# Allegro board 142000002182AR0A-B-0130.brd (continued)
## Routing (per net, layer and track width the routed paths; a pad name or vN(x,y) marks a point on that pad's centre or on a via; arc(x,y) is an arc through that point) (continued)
FAN6_SENSOR_OUT: length 312.7
  TOP w0.127: 136.37,18.36 135.83,18.91 135.05,18.91 U7.B7
  TOP w0.254: v3(406.44,36.45) 406.4,36.45 405.38,37.47 398.48,37.47 396.34,39.61 392.09,39.61 390.41,41.29 390.41,42.48 R165.2 ; v3(139.5,19.28) 139.47,19.28 139.24,19.05 138.68,19.05 138,18.36 136.37,18.36
  BOTTOM w0.254: v3(139.5,19.28) 139.8,19.58 140.87,19.58 141.22,19.94 142.72,19.94 143.69,18.97 147.49,18.97 150.11,16.35 150.11,16.34 150.45,16 v1(153.29,16) 154.69,14.61 154.69,10.92 156.71,8.89 174.12,8.89 178.97,13.74 241.88,13.74 244.39,16.26 295.31,16.26 297.67,13.89 335.47,13.89 340.68,19.1 378.05,19.1 385.87,26.92 390.63,26.92 399.31,35.61 405.6,35.61 v3(406.44,36.45)
FAN6_SENSOR_OUT_R: length 8.7
  TOP w0.254: R165.1 v3(390.78,44.83)
  BOTTOM w0.254: U21.1 391.27,48.12 390.78,47.62 v3(390.78,44.83) 390.02,44.83 v1(389.76,45.09)
FAN6F_VCP: length 3.8
  TOP w0.254: C131.2 385.7,28.96 v3(384.68,29.97) 384.29,30.36 U22.4
  BOTTOM w0.254: v1(385.7,29.97) v3(384.68,29.97)
FAN6R_VCP: length 3.5
  TOP w0.254: v1(375.72,28.07) v3(374.93,28.86) 374.64,29.15 U19.4
  BOTTOM w0.254: v3(374.93,28.86) v1(375.72,28.07)
FAN7_LED_G: length 141.9
  TOP w0.254: U7.K11 v2(127.88,14.94) ; CONN1.5 v3(5.29,32.98)
  BOTTOM w0.254: v3(5.29,32.98) 7.03,31.24 v1(7.03,29.21) 7.03,28.46 9.08,26.42 13.76,26.42 21.51,18.67 27.18,18.67 28.19,17.65 48.22,17.65 51.78,21.21 79.37,21.21 91.51,9.07 114.86,9.07 118.11,12.32 123.74,12.32 125.77,14.35 127.29,14.35 v2(127.88,14.94)
FAN7_LED_R: length 143.4
  TOP w0.254: v3(128.79,11.67) 129.08,11.96 U7.J13 ; v3(5.21,31.62) 5.29,31.71 CONN1.7
  BOTTOM w0.254: v3(128.79,11.67) 125.24,11.67 125.1,11.81 118.32,11.81 115.07,8.56 91.3,8.56 79.15,20.7 51.99,20.7 48.43,17.14 27.98,17.14 26.97,18.16 21.3,18.16 13.68,25.78 8.64,25.78 v1(7.24,27.17) 4.83,29.59 4.83,31.24 v3(5.21,31.62)
FAN7_PRESENT: length 155.6
  TOP w0.127: 131.06,13.21 131.06,14.16 U7.G12
  TOP w0.254: v3(131.3,9.09) 131.18,9.09 130.64,9.63 130.64,11.13 131.06,11.55 131.06,13.21 ; v3(12.32,11.56) 12.45,11.43 12.45,10.54 12.83,10.16 15.57,10.16 15.82,10.41 R4.1 24.38,11.05 v3(26.04,9.4) ; CONN1.21 v3(5.25,22.82)
  BOTTOM w0.254: v3(131.3,9.09) 131.18,9.09 130.09,8 126.03,8 123.85,5.82 91.16,5.82 78.31,18.67 52.83,18.67 49.27,15.11 31.75,15.11 v1(30.26,13.62) v3(26.04,9.4) ; v3(5.25,22.82) 6.14,22.82 7.24,21.72 7.24,15.5 11.44,11.3 12.06,11.3 v3(12.32,11.56)
FAN7_PWM: length 135.4
  TOP w0.254: Q2.2 17.97,38.48 v3(20.06,36.39) ; U7.L4 v2(127.08,20.54)
  BOTTOM w0.254: v3(20.06,36.39) 18.77,35.1 18.77,33.12 16.38,30.73 16.38,26.67 22.35,20.7 43.47,20.7 v1(48.05,25.27) 49.42,23.9 79.55,23.9 84.27,19.18 111.97,19.18 114.13,21.34 121.39,21.34 123.7,19.02 124.17,19.02 125.59,20.45 126.99,20.45 v2(127.08,20.54)
FAN7_SENSOR_IN: length 138.3
  TOP w0.254: U7.M13 126.57,13.74 125.68,12.86 125.64,12.86 124.74,11.96 119.45,11.96 119.42,11.94 110.23,11.94 106.57,15.6 85.56,15.6 84.64,16.51 79.18,21.97 51.6,21.97 47.13,17.5 19.28,17.5 v3(16.89,15.11) R1.1 ; v3(5.21,27.94) 5.25,27.9 CONN1.13
  BOTTOM w0.254: v3(16.89,15.11) 16.89,15.37 v1(16.26,16) 11.68,20.57 11.68,21.64 7.03,26.29 6.86,26.29 v3(5.21,27.94)
FAN7_SENSOR_OUT: length 140.8
  TOP w0.127: U7.L12 127.08,14.14 127.08,13.52 126.86,13.31
  TOP w0.254: CONN1.15 5.25,26.63 v3(5.21,26.67) ; 126.86,13.31 125.62,12.06 125.48,12.06 124.87,11.46 119.66,11.46 119.63,11.43 110.02,11.43 106.36,15.09 85.35,15.09 84.43,16 78.97,21.46 51.87,21.46 47.39,16.99 20.29,16.99 v3(17.15,13.84) R2.1
  BOTTOM w0.254: v3(5.21,26.67) 6.22,25.65 6.95,25.65 11.18,21.43 11.18,20 v1(12.1,19.08) 12.1,18.97 17.15,13.92 v3(17.15,13.84)
FAN8_LED_G: length 130.1
  TOP w0.127: 125.22,17.02 125.51,17.31 126.25,17.31 U7.M8
  TOP w0.254: 125.22,17.02 123.95,17.02 123.16,16.23 112.56,16.23 108.62,20.17 87.45,20.17 81.08,26.54 53.09,26.54 v3(48.77,22.23) 47.5,22.23 45.59,20.32 19.43,20.32 14.48,25.27 14.48,28.7 12.74,30.44 CONN1.10
  BOTTOM w0.254: v3(48.77,22.23) v1(49.41,21.58)
FAN8_LED_R: length 128.9
  TOP w0.254: U7.N9 125.32,16.38 123.83,16.38 123.16,15.72 112.05,15.72 108.11,19.66 87.24,19.66 80.87,26.04 53.51,26.04 49.04,21.56 47.98,21.56 v3(46.86,20.45) 46.23,19.81 19.22,19.81 13.97,25.06 13.97,28.49 13.29,29.17 CONN1.12
  BOTTOM w0.254: v3(46.86,20.45) v1(45.95,20.45)
FAN8_PRESENT: length 142.2
  TOP w0.127: 130.05,12.56 130.05,13.33 130.27,13.55 130.27,15.73 U7.G10
  TOP w0.254: v3(127.75,9.41) 129,10.67 129.05,10.67 130.01,11.62 130.01,12.52 130.05,12.56 ; CONN1.24 12.36,21.55 13.33,20.58 13.33,13.36 13.59,13.11 15.57,13.11 15.82,12.85 R3.1 24.77,12.45 v3(25.53,13.21)
  BOTTOM w0.254: v3(25.53,13.21) v1(26.29,13.97) 28.45,16.13 48.85,16.13 52.41,19.68 78.73,19.68 91.59,6.83 123.42,6.83 125.89,9.29 127.63,9.29 v3(127.75,9.41)
FAN8_PWM: length 130.7
  TOP w0.254: v3(14.86,30.35) 15.24,30.74 15.24,34.32 Q1.2 ; U7.L5 v2(127.08,19.74)
  BOTTOM w0.254: v3(14.86,30.35) 15.2,30.01 15.2,26.42 21.93,19.68 27.81,19.68 v1(29.08,18.41) 29.34,18.67 42.88,18.67 47.1,22.89 79.13,22.89 83.85,18.16 112.39,18.16 114.55,20.32 120.97,20.32 123.28,18.01 124.21,18.01 125.94,19.74 v2(127.08,19.74)
FAN8_SENSOR_IN: length 127.6
  TOP w0.127: 125.35,15.88 125.45,15.77 126.31,15.77 U7.M10
  TOP w0.254: CONN1.18 12.11,25.36 14.77,22.69 14.77,20.32 15.02,20.07 R5.1 15.04,20.25 15.52,20.73 17.59,20.73 19.01,19.3 47.5,19.3 52.71,24.51 80.23,24.51 86.61,18.14 108.7,18.14 v3(111.23,15.6) 111.62,15.21 123.29,15.21 123.95,15.88 125.35,15.88
  BOTTOM w0.254: v1(110.74,16.51) 110.74,16.09 v3(111.23,15.6)
FAN8_SENSOR_OUT: length 126.6
  TOP w0.254: U7.N11 125.74,15.48 124.48,15.48 123.7,14.71 111.2,14.71 v3(109.22,16.68) 108.28,17.63 86.4,17.63 80.02,24 52.92,24 46.92,18.01 15.29,18.01 15.04,18.26 R6.1 13.97,19.74 13.97,22.23 12.11,24.09 CONN1.20
  BOTTOM w0.254: v1(108.29,16.69) 108.3,16.68 v3(109.22,16.68)
FAN_12V: length 55.2
  TOP w0.254: 378.33,5.46 378.2,5.6 U20.9
  TOP w0.381: 381.63,25.02 381.58,24.97 C127.2 ; v3(379.65,25.46) 379.65,25.45 379.71,25.4 379.71,25.04 379.78,24.97 C127.2 ; L26.1 380.62,25.53 C127.2 ; L20.1 304.35,22.91 C101.2 305.56,22.1 ; L24.1 368.61,28.27 C117.2 367.03,29.84 v3(366.9,29.72) ; v3(313.72,21.59) 314.07,21.95 C108.2 315.03,22.53 315.09,22.48 ; R12.2 42.55,41.4 43.16,40.79 43.16,37.68 44.07,36.77 L4.1
  TOP w0.508: C13.2 36.76,25.71 36.7,25.65 ; C13.2 38.68,25.71 v3(38.73,25.65) ; C13.2 37.85,25.33 v3(37.85,24.77) ; C32.2 104.45,30.66 104.52,30.73 ; C32.2 103.3,30.66 v3(102.74,30.1) ; C32.2 103.63,29.46 L7.1 ; C65.1 211.43,24.74 C67.1 212.12,24.36 212.22,24.26 ; C88.2 241.05,30.1 L18.1 ; C88.2 241.63,31.55 241.81,31.37 ; C88.2 240.34,31.55 ; 166.8,25.71 C46.2 ; C46.2 165.66,25.71 165.48,25.53 ; C46.2 166.12,25.02 ; 175.01,25.53 175.19,25.71 C54.2 ; C68.1 213.13,24.66 213.11,24.64 ; 86.36,38.86 86.41,38.81 C25.2 ; 392.81,6.99 392.94,6.86 C136.1 393.12,5.84 394.08,5.84 ; C135.1 391.8,6.86 ; 378.33,5.46 378.33,5.46 380.91,5.46 D3.C ; 389.64,5.71 389.69,5.66 C134.1 390.65,6.73 390.78,6.86 ; C25.2 86.41,37.01 v3(86.36,36.96) ; C25.2 86.03,37.85 v3(85.47,37.85) ; v3(27.81,24.89) 27.81,25.33 C5.2 26.92,25.2 v3(26.92,24.89) ; 223.45,38.43 C78.2 ; R119.2 v3(225.7,24.61) ; C54.2 175.64,25.02 ; C54.2 176.33,25.71
  vias: v1(35.56,24.64) v1(96.77,31.5) v1(166.5,24.89) v1(240.28,30.23) v1(371.98,7.62) v3(26.92,24) v3(27.81,24) v3(28.83,24.89) v3(33.66,34.77) v3(34.47,34.77) v3(35.2,36.88) v3(35.2,36.07) v3(35.2,35.26) v3(36.96,24.77) v3(38.73,24.77) v3(38.73,23.88) v3(43.69,34.77) v3(44.5,34.77) v3(45.24,36.88) v3(45.24,36.07) v3(45.24,35.26) v3(84.58,36.96) v3(85.47,38.73) v3(85.47,36.96) v3(95.48,32) v3(95.48,31.19) v3(95.89,30.35) v3(96.77,30.35) v3(97.66,30.35) v3(101.85,30.1) v3(101.85,29.21) v3(102.74,29.21) v3(102.74,28.32) v3(111,36.68) v3(111.81,36.68) v3(112.93,38.79) v3(112.93,37.97) v3(112.93,37.16) v3(165.74,23.88) v3(166.62,23.88) v3(167.64,25.65) v3(167.64,24.77) v3(167.64,23.88) v3(172.21,34.77) v3(173.02,34.77) v3(173.89,36.4) v3(173.89,35.59) v3(173.89,34.77) v3(175.26,23.88) v3(176.15,23.88) v3(177.16,25.65) v3(177.16,24.77) v3(177.16,23.88) v3(181.74,34.77) v3(182.55,34.77) v3(183.41,36.4) v3(183.41,35.59) v3(183.41,34.77) v3(209.07,25.12) v3(209.07,24.23) v3(221.49,38.35) v3(221.49,37.47) v3(222.38,38.35) v3(222.38,37.47) v3(222.38,36.58) v3(232.51,31.62) v3(232.51,30.81) v3(232.99,30.07) v3(233.81,30.07) v3(234.62,30.07) v3(238.38,31.24) v3(238.38,30.35) v3(238.38,29.34) v3(239.4,30.86) v3(239.4,29.72) v3(248.03,37.57) v3(248.84,37.57) v3(249.58,39.67) v3(249.58,38.86) v3(249.58,38.05) v3(303.28,21.31) v3(304.29,21.31) v3(305.44,21.59) v3(306.15,21.05) v3(306.32,21.84) v3(306.37,22.73) v3(307.35,34.81) v3(307.61,35.58) v3(308.08,36.25) v3(308.24,34.72) v3(308.51,35.49) v3(311.66,20.7) v3(312.55,20.7) v3(313.56,20.7) v3(314.45,20.7) v3(314.71,21.59) v3(318.04,34.29) v3(318.16,33.33) v3(318.36,32.54) v3(318.52,35.18) v3(318.77,33.92) v3(362.2,29.72) v3(362.33,28.91) v3(363.35,29.72) v3(363.35,28.91) v3(364.24,29.72) v3(364.36,28.92) v3(365,7.75) v3(365,6.48) v3(365,4.95) v3(365,3.56) v3(365.12,29.72) v3(365.25,28.92) v3(366.09,29.72) v3(366.14,28.7) v3(366.39,6.48) v3(366.39,3.56) v3(366.52,7.75) v3(366.52,4.95) v3(367.16,28.7) v3(368.17,7.75) v3(368.17,6.48) v3(368.17,4.95) v3(368.17,3.56) v3(376.96,38.77) v3(376.96,36.17) v3(377.57,35.43) v3(377.77,38.76) v3(377.94,36.17) v3(378.84,25.4) v3(378.95,26.35) v3(379.53,26.92) v3(379.93,26.22) v3(380.34,26.92) v3(383.69,6.05) v3(383.77,7.67) v3(383.79,6.86) v3(384.49,6.18) v3(384.6,6.99) v3(384.81,7.79) v3(385.31,6.15) v3(385.41,6.97) v3(385.62,7.76) v3(386.13,6.16) v3(386.33,6.94) v3(386.46,7.75) v3(388.52,39.88) v3(388.63,38.73) v3(388.65,37.59) v3(389.32,39.75) v3(389.44,38.83) v3(389.46,37.59)
FAN_12V_PDU: length 28.4
  TOP w0.508: C139.1 401.19,19.81 ; 402.21,19.81 C140.1 403.17,20.75 403.23,20.7 ; 400.18,19.81 C137.1 400.12,20.7 399.16,20.7 ; R152.2 v3(374.98,13.01)
  BOTTOM w0.508: v3(393.45,10.79) 388.49,10.79 386.94,9.25 378.36,9.25 377.85,9.75 v1(374.98,9.75) v3(374.98,13.01)
  vias: v1(392.43,18.92) v1(392.81,22.48) v1(394.46,15.49) v1(395.35,22.61) v1(395.73,19.68) v3(395.86,10.67) v3(396.88,21.84) v3(396.88,20.45) v3(396.88,18.92) v3(396.88,17.14) v3(397.26,16.13) v3(398.14,19.56) v3(398.14,18.03) v3(398.14,10.79) v3(398.27,21.08) v3(399.03,15.62) v3(399.03,13.72) v3(399.16,11.81) v3(399.42,19.05) v3(399.67,17.4) v3(400.69,13.59) v3(400.81,15.24) v3(400.81,11.68) v3(400.94,18.92) v3(401.83,14.22) v3(402.08,17.4) v3(402.46,15.62) v3(402.97,19.05) v3(403.99,17.4) v3(404.11,15.62) v3(404.37,20.07) v3(405.38,14.35) v3(405.76,17.4) v3(405.89,19.18)
FAN_BOT_HS_PGD: length 338.4
  TOP w0.254: v3(379.6,2.16) 379.6,4.19 379.28,4.52 R157.1 C125.1 377.7,4.65 377.7,5.13 v3(377.49,5.33) 377.7,5.54 U20.8 ; CONN2.18 65.49,12.37 66.04,11.81 v3(66.04,11.68) ; v3(71.16,10.88) 78.53,10.88 83.06,6.35 104.43,6.35 106.48,4.29 123.77,4.29 126.1,1.96 174.9,1.96 183.23,10.29 224.31,10.29 v3(226.69,7.9)
  BOTTOM w0.254: v3(66.04,11.68) 66.42,11.3 v1(70.1,11.3) 70.74,11.3 v3(71.16,10.88) ; v3(379.6,2.16) 379.48,2.03 363.98,2.03 355.35,10.67 330.75,10.67 328.59,8.51 295.83,8.51 293.16,11.18 246.5,11.18 243.98,8.66 227.45,8.66 v3(226.69,7.9)
  BOTTOM w0.381: v3(377.49,5.33) v1(378.46,5.33)
FAN_IN_3V3_25M_EN: length 3.6
  TOP w0.254: R66.2 v3(133.48,32.77) 132.59,32.77 OSC1.1
  BOTTOM w0.254: v3(133.48,32.77) 133.86,32.77 v1(134.49,33.4)
FAN_IN_3V3_25M_VCC: length 6
  TOP w0.508: OSC1.4 132.29,30.53 v3(133.43,30.53) C40.1 135.05,30.53 136.01,31.5 L10.1
  BOTTOM w0.254: v3(133.43,30.53) 133.4,30.56 133.4,31.45 v1(133.22,31.62)
FAN_INT_L: length 93.7
  TOP w0.127: U7.F12 131.89,14.14 131.89,13.23
  TOP w0.254: v3(132.62,8.94) 131.96,9.6 131.96,11.93 131.89,12 131.89,13.23 ; CONN2.1 v3(55.33,7.79)
  BOTTOM w0.254: v3(132.62,8.94) 132.62,8.76 130.85,6.99 126.45,6.99 124.27,4.8 89.31,4.8 81.05,13.06 v1(66.8,13.06) 66.27,13.06 60.07,6.86 56.01,6.86 55.33,7.54 v3(55.33,7.79)
FAN_SCL1_R: length 14.7
  TOP w0.127: 127.88,13.01 127.88,14.14 U7.K12
  TOP w0.254: v3(121.79,9.65) 122.64,10.5 125.39,10.5 127.88,12.99 127.88,13.01 ; R57.1 v3(118.11,9.65) R45.1
  BOTTOM w0.254: v3(118.11,9.65) 119,9.65 v1(119.25,9.91) 119.29,9.94 121.5,9.94 v3(121.79,9.65)
FAN_SCL2_R: length 14.6
  TOP w0.254: U7.K13 128.28,13.09 128.23,13.05 128.23,12.62 125.69,10.08 123.32,10.08 v3(123.23,9.99) ; R58.1 v3(118.11,8.51) R46.1
  BOTTOM w0.254: v3(118.11,8.51) v1(121.16,8.51) 121.75,8.51 v3(123.23,9.99)
FAN_SDA1_R: length 13.3
  TOP w0.254: R56.1 v3(118.11,10.67) R44.1 ; U7.L13 127.48,13.31 125.03,10.86 121.94,10.86 v3(121.67,10.58)
  BOTTOM w0.254: v3(118.11,10.67) 118.49,11.05 v1(120.78,11.05) 120.93,11.2 121.41,11.2 121.67,10.95 v3(121.67,10.58)
FAN_SDA2_R: length 17.7
  TOP w0.127: 128.68,13 128.71,13.04 128.71,14.17 U7.J12
  TOP w0.254: v3(123.95,9.27) 123.95,9.27 125.48,9.27 128.68,12.47 128.68,13 ; R47.1 v3(118.11,7.49) R59.1
  BOTTOM w0.254: v3(123.95,9.27) 122.17,7.49 v3(118.11,7.49) 117.32,7.49 v1(117.04,7.77)
FAN_SDA_1_E: length 5.9
  TOP w0.254: U8.15 153.97,21.27 153.59,21.65 152.72,21.65 151.77,20.71 v3(151.25,20.71) 151.22,20.68 R89.2
  BOTTOM w0.254: v3(151.25,20.71) v1(150.5,21.46)
FAN_SDA_1_R: length 12.4
  TOP w0.127: 136.56,15.09 135.9,15.75 135.09,15.75 U7.B11
  TOP w0.254: 136.56,15.09 137.23,15.09 137.61,14.71 139.32,14.71 141.29,12.74 v3(141.73,12.74) 143.42,11.05 R81.1
  BOTTOM w0.254: v1(141.26,11.96) 141.26,12.27 v3(141.73,12.74)
FAN_TOP_HS_PGD: length 73.1
  TOP w0.254: CONN1.29 5.8,17.74 5.4,17.34 5.4,12.81 9.58,8.64 26.42,8.64 30.38,12.6 44.93,12.6 45.41,12.12 R16.1 v3(46.48,11.94) ; v3(64.22,15.68) CONN2.16
  BOTTOM w0.254: v3(64.22,15.68) 63.26,16.64 54.18,16.64 v1(49.48,11.94) v3(46.48,11.94)
FB_VDD3P3: length 6.5
  TOP w0.381: U12.5 222.91,21.44 223.04,21.56 R120.1 223.98,20.98 223.93,20.93 C79.2 R122.1 v3(225.83,20.24)
  BOTTOM w0.381: v3(225.83,20.24) v1(225.83,21.18)
GPIO_1: length 11.9
  TOP w0.254: U7.B1 134.8,23.34 135.54,24.08 136.35,24.08 137.03,24.77 138.39,24.77 v3(139.81,26.18) 140.37,26.75 142.04,26.75 142.55,26.24 R72.2 R73.1
  BOTTOM w0.254: v3(139.81,26.18) 140.82,26.18 v1(140.83,26.17)
HS_GATE: length 19.4
  TOP w0.254: 378.7,7.4 U20.10
  TOP w0.508: U23.4 387.51,15.62 v3(388.24,15.62) ; v3(378.84,10.03) 378.84,7.55 378.7,7.4
  BOTTOM w0.508: v3(378.84,10.03) 378.87,10.01 386.63,10.01 387.86,11.24 v1(387.86,11.81) 388.24,12.19 v3(388.24,15.62)
HS_MOS_D:
  vias: v1(381.63,14.86) v3(381.2,17.32) v3(381.2,16.4) v3(381.33,18.54) v3(381.39,19.35) v3(382.02,17.32) v3(382.02,16.38) v3(382.14,18.54) v3(382.52,19.43) v3(383.29,20.7) v3(383.29,17.45) v3(383.29,16.38) v3(383.41,18.54) v3(383.67,19.56) v3(384.56,18.41) v3(384.56,17.32) v3(384.56,16.51) v3(384.68,20.83) v3(384.88,22.02)
HS_OV: length 5.6
  TOP w0.254: U20.4 377.2,12.06 377.18,12.07 377.18,12.76 R154.1 376.94,12.94 v3(376.01,12.01) R151.2
  BOTTOM w0.254: v3(376.01,12.01) 376.43,12.43 v1(376.43,12.95)
HS_PWR: length 3.1
  TOP w0.254: R153.2 376.81,5.21 v3(376.68,5.33) 377.2,5.85 U20.7
  BOTTOM w0.254: v3(376.68,5.33) v1(376.68,6.35)
HS_SENSE: length 29
  TOP w0.254: U20.1 378.7,11.68 378.71,11.68 378.71,13.76 v3(378.89,13.94) 379,13.94 379.98,14.93 379.98,20.66 384.07,24.74 384.07,26.18 384.88,26.99 389.83,26.99 390.27,26.54 390.27,25.65 390.07,25.45 R164.1
  BOTTOM w0.254: v1(378.97,12.7) 378.97,13.87 v3(378.89,13.94)
HS_TIMER: length 3.6
  TOP w0.254: C122.1 v3(375.79,5.32) 375.79,6.1 376.06,6.36 U20.6
  BOTTOM w0.381: v3(375.79,5.32) v1(374.79,5.32)
HS_UV: length 6.3
  TOP w0.254: U20.3 377.69,11.17 377.69,13.66 377.44,13.92 R154.2 R152.1 375.92,14.59 v3(376.05,14.72)
  BOTTOM w0.254: v1(375.67,15.62) 376.05,15.24 v3(376.05,14.72)
HS_VIN: length 32.7
  TOP w0.254: R164.2 390.98,25.45 390.78,25.65 390.78,26.75 390.04,27.5 384.67,27.5 383.56,26.39 383.56,24.96 379.48,20.87 379.48,18.16 378.21,16.89 D2.C 379.29,16.57 379.48,16.38 379.48,15.14 378.94,14.61 v3(378.42,14.61) 378.2,14.39 U20.2
  BOTTOM w0.254: v3(378.42,14.61) 378.21,14.82 v1(378.21,15.62)
I2C_ FAN_MNGMT_SCL: length 136.2
  TOP w0.254: R20.2 57.71,4.72 57.72,4.72 59.4,3.05 65.15,3.05 69.22,7.11 69.22,10.54 70.57,11.9 78.95,11.9 83.48,7.37 104.85,7.37 106.9,5.31 124.19,5.31 126.53,2.97 137.97,2.97 138.99,3.99 v3(138.99,6.19) ; U7.A10 136.03,16.14 136.45,15.72 140.19,15.72 143.85,12.06 145.51,12.06 v3(145.54,12.03) 145.57,12.06 146.19,12.06 148.02,13.9 148.02,21.15 149.1,22.23 153.92,22.23 154.62,21.53 U8.14
  BOTTOM w0.254: v3(138.99,6.19) 141.22,8.42 v1(143.51,8.42) 144.6,8.42 146.46,10.27 146.46,11.66 146.08,12.03 v3(145.54,12.03)
I2C_ FAN_MNGMT_SDA: length 112.8
  TOP w0.254: R24.2 59.24,4.65 59.82,4.06 64.73,4.06 68.2,7.53 68.2,10.97 70.29,13.06 79.23,13.06 83.9,8.38 105.27,8.38 107.33,6.32 124.61,6.32 126.95,3.99 136.75,3.99 137.82,5.06 137.82,6.53 v3(138.23,6.94) ; R81.2 v3(145.8,11.05) 146.61,11.05 149.03,13.48 149.03,20.33 R89.1
  BOTTOM w0.254: v3(138.23,6.94) 138.3,6.94 141.65,10.29 v1(143.89,10.29) 145.03,10.29 v3(145.8,11.05)
I2C_FAN_BOT_SCL: length 62.7
  TOP w0.254: R22.2 59.69,19.05 60.58,19.94 78.22,19.94 85.08,13.08 v3(98.5,13.08) 105.28,13.08 108.71,9.65 R45.2
  BOTTOM w0.254: v3(98.5,13.08) v1(99.42,13.08)
I2C_FAN_BOT_SDA: length 64.7
  TOP w0.254: R44.2 109.35,10.67 v3(106.55,13.46) 105.44,14.58 85.14,14.58 78.76,20.95 59.94,20.95 58.17,19.18 R21.2
  BOTTOM w0.254: v1(105.91,14.11) v3(106.55,13.46)
I2C_FAN_TOP_SCL: length 58
  TOP w0.254: R25.2 77.93,18.8 84.79,11.94 v3(95.89,11.94) 104.99,11.94 108.42,8.51 R46.2
  BOTTOM w0.254: v3(95.89,11.94) v1(95.89,12.85)
I2C_FAN_TOP_SDA: length 58.1
  TOP w0.254: R26.2 77.51,17.78 84.65,10.64 v3(95.89,10.64) 104.44,10.64 107.59,7.49 R47.2
  BOTTOM w0.254: v3(95.89,10.64) v1(94.87,10.64)
I2C_SCL_LC1_R: length 5
  TOP w0.254: CONN2.8 59.14,15.68 v3(59.13,15.68) 59.13,15.83 59.69,16.38 R22.1
  BOTTOM w0.254: v3(59.13,15.68) v1(59.13,14.76)
I2C_SCL_LC2_R: length 7
  TOP w0.254: R25.1 62.1,18.8 61.11,17.81 v3(61.11,15.72) 61.68,15.16 CONN2.12
  BOTTOM w0.254: v1(61.11,14.81) v3(61.11,15.72)
I2C_SCL_MNGMT: length 13.3
  TOP w0.254: v3(56.44,15.75) 56.44,14.03 CONN2.4 ; v3(57.08,7.62) 57.08,6.91 56.7,6.53 R19.1 R20.1
  BOTTOM w0.254: v3(57.08,7.62) 57.08,9.85 56.44,10.49 v1(56.44,14.73) v3(56.44,15.75)
I2C_SDA_LC1_R: length 16.7
  TOP w0.254: R21.1 56.35,17.71 54.36,15.71 v3(54.36,13.97) 54.36,12.65 55.07,11.94 59.52,11.94 60.41,11.05 CONN2.9
  BOTTOM w0.254: v1(53.97,13.08) 54.36,13.47 v3(54.36,13.97)
I2C_SDA_LC2_R: length 8.6
  TOP w0.254: v3(62.36,11.81) 62.95,11.22 CONN2.13 ; v3(63.02,15.72) 62.66,16.08 R26.1
  BOTTOM w0.254: v3(63.02,15.72) 62.34,15.04 v1(62.34,12.83) 62.34,11.83 v3(62.36,11.81)
I2C_SDA_MNGMT: length 7.3
  TOP w0.254: R24.1 R23.1 60.14,6.25 59.41,6.99 58.67,6.99 58.31,7.35 v3(58.31,7.95) 57.87,8.4 CONN2.5
  BOTTOM w0.254: v3(58.31,7.95) v1(58.31,8.89)
ILIM_FAN1F: length 3.5
  TOP w0.254: U3.5 42.9,29.61 v3(42.93,29.59) 42.93,29.21 43.38,28.76 R13.2
  BOTTOM w0.254: v1(43.94,29.59) v3(42.93,29.59)
ILIM_FAN1R: length 3.4
  TOP w0.254: R8.2 33.6,28.76 32.89,29.46 v3(32.89,29.59) 32.87,29.61 U1.5
  BOTTOM w0.254: v1(33.91,29.59) v3(32.89,29.59)
ILIM_FAN2F: length 3.5
  TOP w0.254: U6.5 110.21,31.52 v3(110.24,31.5) 110.24,31.11 110.69,30.66 R35.2
  BOTTOM w0.254: v1(111.25,31.5) v3(110.24,31.5)
ILIM_FAN2R: length 3.6
  TOP w0.254: U4.5 90.42,33.57 90.42,32.89 v3(90.3,32.77) 89.92,32.77 89.46,32.31 R30.2
  BOTTOM w0.254: v1(90.3,31.75) v3(90.3,32.77)
ILIM_FAN3F: length 3.5
  TOP w0.254: U11.5 181.08,29.61 v3(181.1,29.59) 181.1,29.21 181.56,28.76 R110.2
  BOTTOM w0.254: v1(182.12,29.59) v3(181.1,29.59)
ILIM_FAN3R: length 3.5
  TOP w0.254: R105.2 172.03,28.76 171.58,29.21 v3(171.58,29.59) 171.55,29.61 U9.5
  BOTTOM w0.254: v1(172.59,29.59) v3(171.58,29.59)
ILIM_FAN4F: length 3.5
  TOP w0.254: R128.2 247.72,31.55 247.27,32 v3(247.27,32.38) 247.25,32.41 U15.5
  BOTTOM w0.254: v1(248.28,32.38) v3(247.27,32.38)
ILIM_FAN4R: length 3.5
  TOP w0.254: U13.5 227.35,32.41 v3(227.33,32.38) 226.95,32.38 226.49,31.93 R123.2
  BOTTOM w0.254: v1(227.33,31.37) v3(227.33,32.38)
ILIM_FAN5F: length 3.4
  TOP w0.254: v1(316.48,26.85) 315.41,26.85 v3(315.22,27.04) 315.06,27.2 U18.5
  BOTTOM w0.254: v3(315.22,27.04) 315.41,26.85 v1(316.48,26.85)
ILIM_FAN5R: length 3
  TOP w0.254: v1(308.36,27.36) 307.54,27.36 v3(307.34,27.56) 307.32,27.58 U16.5
  BOTTOM w0.254: v1(308.36,27.36) 307.54,27.36 v3(307.34,27.56)
ILIM_FAN6F: length 3.4
  TOP w0.254: R160.2 386.53,30.28 v3(385.8,31.01) U22.5
  BOTTOM w0.254: v3(385.8,31.01) 385.7,31.11 v1(385.7,32.13)
ILIM_FAN6R: length 3.2
  TOP w0.254: R155.2 376.5,29.26 v3(376.05,29.72) 375.77,29.99 U19.5
  BOTTOM w0.254: v1(377.06,29.72) v3(376.05,29.72)
LGND_FAN12V: length 59.5
  TOP w0.254: 376.19,11.16 U20.5
  TOP w0.381: C137.2 398.96,21.66 396.37,24.26 396.37,26.54 394.84,28.07 384.43,28.07 382.99,26.62 382.99,25.19 380.28,22.48 376.68,22.48 371.98,17.79 v3(371.98,15.37) 371.98,10.79 372.36,10.41 R149.1 ; R149.1 373.38,5.75 375.52,3.61 C122.2 R153.1 ; R149.1 374.22,10.41 R151.1 376.13,11.1 376.19,11.16
  BOTTOM w0.381: v1(373,15.37) v3(371.98,15.37)
LGND_VDD3P3: length 10.5
  TOP w0.508: C76.2 222.6,26.76 223.35,26.01 R118.2 225.42,26.01 226.59,24.84 v3(226.59,22.33) 225.83,21.56 R120.2
  BOTTOM w0.381: v3(226.59,22.33) v1(226.59,23.34)
PCA9534PW_A0: length 8
  TOP w0.254: U8.1 153.25,13.43 152.64,12.81 150.74,12.81 v3(150.08,12.15) 149.96,12.04 R90.1 R91.1
  BOTTOM w0.254: v3(150.08,12.15) v1(150.08,11.05)
PCA9534PW_A1: length 7
  TOP w0.254: R94.1 R93.1 v3(151.99,12.15) 152.74,12.15 153.97,13.38 U8.2
  BOTTOM w0.254: v3(151.99,12.15) 151.99,12.73 v1(151.51,13.21)
PCA9534PW_A2: length 5.9
  TOP w0.254: U8.3 154.62,13.02 v3(153.75,12.15) 154.03,11.88 R95.1 R96.1
  BOTTOM w0.254: v1(153.75,11.18) v3(153.75,12.15)
PWM_OUT1: length 6.6
  TOP w0.254: Q3.G 45.17,37.59 45.97,37.59 46.67,36.89 Q4.4 v3(48.77,36.89)
  BOTTOM w0.254: v3(48.77,36.89) v1(48.77,35.81)
PWM_OUT2: length 4.1
  TOP w0.254: Q5.G 117.03,36.9 v3(116.84,36.7) 116.68,36.54 Q6.4
  BOTTOM w0.254: v3(116.84,36.7) v1(116.84,35.69)
PWM_OUT3: length 3.8
  TOP w0.254: Q8.4 185.26,36.54 v3(185.29,36.58) 185.74,37.02 Q7.G
  BOTTOM w0.254: v3(185.29,36.58) v1(185.29,37.59)
PWM_OUT4: length 4.3
  TOP w0.254: Q10.4 251.3,36.29 v3(251.71,36.7) 252.03,37.02 Q9.G
  BOTTOM w0.254: v1(251.71,37.72) v3(251.71,36.7)
PWM_OUT5: length 3.9
  TOP w0.254: v1(319.98,33.42) v3(319.98,32.26) 319.98,31.94 320.23,31.68 Q12.4
  BOTTOM w0.254: v1(319.98,33.42) v3(319.98,32.26)
PWM_OUT6: length 3.4
  TOP w0.254: Q13.G 391.76,35.55 v3(391.76,35.2) Q14.4
  BOTTOM w0.254: v1(391.67,36.45) 391.76,36.35 v3(391.76,35.2)
PWM_OUT7: length 10.9
  TOP w0.254: Q2.4 15.08,38.88 14.86,38.66 v3(10.97,38.66) 7.83,35.52 CONN1.1
  BOTTOM w0.254: v3(10.97,38.66) 10.92,38.61 10.16,38.61 v1(10.03,38.48)
PWM_OUT8: length 6
  TOP w0.254: Q1.4 13.62,32.23 13.21,32.64 v3(13.21,32.89) 13.21,33.82 12.77,34.25 CONN1.4
  BOTTOM w0.254: v1(12.19,33.02) 13.08,33.02 v3(13.21,32.89)
SS_VDD3P3: length 2.6
  TOP w0.381: C76.1 221.69,26.64 221.68,26.63 v3(221.68,26.04) U12.8
  BOTTOM w0.381: v1(222.66,26.01) 221.71,26.01 v3(221.68,26.04)
SST_FAN1F: length 3
  TOP w0.254: U3.6 v3(42.93,32.62) 43.33,32.62 43.49,32.46 C18.2
  BOTTOM w0.254: v1(41.91,32.62) v3(42.93,32.62)
SST_FAN1R: length 2.9
  TOP w0.254: U1.6 v3(32.89,32.62) 33.3,32.62 33.45,32.46 C11.2
  BOTTOM w0.254: v1(31.98,32.62) v3(32.89,32.62)
SST_FAN2F: length 3
  TOP w0.254: U6.6 v3(110.24,34.52) 110.64,34.52 110.8,34.36 C38.2
  BOTTOM w0.254: v1(109.22,34.52) v3(110.24,34.52)
SST_FAN2R: length 3
  TOP w0.254: U4.6 v3(93.32,32.77) 93.32,32.23 93.16,32.08 C27.2
  BOTTOM w0.254: v1(93.32,33.78) v3(93.32,32.77)
SST_FAN3F: length 3
  TOP w0.254: U11.6 v3(181.1,32.62) 181.51,32.62 181.66,32.46 C59.2
  BOTTOM w0.254: v1(182.12,32.62) v3(181.1,32.62)
SST_FAN3R: length 2.9
  TOP w0.254: U9.6 v3(171.58,32.62) 171.98,32.62 172.14,32.46 C52.2
  BOTTOM w0.254: v1(170.66,32.62) v3(171.58,32.62)
SST_FAN4F: length 2.9
  TOP w0.254: U15.6 v3(247.27,35.41) 247.67,35.41 247.83,35.25 C94.2
  BOTTOM w0.254: v1(248.18,35.41) v3(247.27,35.41)
SST_FAN4R: length 2.9
  TOP w0.254: U13.6 v3(230.35,32.38) 230.35,31.98 230.2,31.82 C83.2
  BOTTOM w0.254: v1(230.35,33.3) v3(230.35,32.38)
SST_FAN5F: length 3.2
  TOP w0.254: v1(316.48,30.05) 316.33,30.2 v3(315.34,30.2) U18.6
  BOTTOM w0.254: v1(316.48,30.05) 315.5,30.05 v3(315.34,30.2)
SST_FAN5R: length 3.1
  TOP w0.254: U16.6 v3(307.34,30.58) 308.2,30.58 C102.2
  BOTTOM w0.254: v3(307.34,30.58) v1(306.06,30.58)
SST_FAN6F: length 3.4
  TOP w0.254: U22.6 v3(385.83,34.01) 386.69,34.01 C132.2
  BOTTOM w0.254: v3(385.83,34.01) 386.69,34.01 v1(387.1,34.42)
SST_FAN6R: length 3.2
  TOP w0.254: U19.6 v3(376.05,33) 376.78,33 C124.2
  BOTTOM w0.254: v3(376.05,33) 376.07,33.02 v1(377.19,33.02)
SW_VDD3P3: length 8.3
  TOP w0.508: 206.63,22.61 R117.2 208.32,21.79 D1.C ; C70.2 v3(215.52,26.92)
  BOTTOM w0.508: v3(215.52,26.92) v1(215.52,24.16) 215.52,23.37 v3(214.76,22.61)
SW_VDD3P3_PLL_C: length 2.8
  TOP w0.508: C64.1 v3(206.63,20.07) R117.1
  BOTTOM w0.254: v3(206.63,20.07) v1(206.63,21.21)
TMP1_CLKOUT_N: length 9.5
  TOP w0.127: 125.48,22.17 126.25,22.17 U7.M3
  TOP w0.254: 125.48,22.17 125.36,22.17 124.95,22.59 123.21,22.59 121.07,24.73 v3(120.87,24.73) 120.87,24.8 120.14,25.53 R52.1
  BOTTOM w0.254: v3(120.87,24.73) v1(119.8,24.73)
TMP1_CLKOUT_P: length 10.1
  TOP w0.127: U7.L3 127.08,21.34 125.6,21.34
  TOP w0.254: 125.6,21.34 125.55,21.39 124.55,21.39 123.84,22.1 122.98,22.1 121.35,23.73 v3(121.01,23.73) 120.93,23.73 120.15,24.51 R53.1
  BOTTOM w0.254: v3(121.01,23.73) 121.77,23.73 v1(121.92,23.88)
VERSION_ID_0: length 12.9
  TOP w0.127: U7.M12 126.26,14.12 125.6,14.12
  TOP w0.254: R49.1 v3(116.71,12.7) R41.2 ; 125.6,14.12 125.37,14.35 v3(125.01,14.35)
  BOTTOM w0.254: v3(116.71,12.7) 116.97,12.95 v1(117.6,12.95) 117.73,12.82 123.44,12.82 124.97,14.35 v3(125.01,14.35)
VERSION_ID_1: length 12
  TOP w0.254: U7.N12 125.57,14.86 124.46,14.86 123.98,14.38 v3(123.98,14.26) ; R40.2 v3(116.71,13.72) R48.1
  BOTTOM w0.254: v3(123.98,14.26) 123.3,13.59 v1(123.06,13.59) 122.68,13.59 122.43,13.33 118.49,13.33 118.11,13.72 v3(116.71,13.72)
VERSION_ID_2: length 10.9
  TOP w0.254: R51.1 v3(117.47,16.89) R43.2 ; U7.N8 125.44,17.74 125.09,17.4 123.59,17.4 v3(122.93,16.74)
  BOTTOM w0.254: v3(117.47,16.89) 117.6,16.89 117.86,16.64 v1(120.65,16.64) 120.88,16.41 122.6,16.41 v3(122.93,16.74)
VREG5_VDD3P3: length 3.8
  TOP w0.381: U12.6 v3(223.16,22.71) 223.29,22.58 C81.1
  BOTTOM w0.381: v1(221.97,22.07) 222.4,22.07 223.04,22.71 v3(223.16,22.71)

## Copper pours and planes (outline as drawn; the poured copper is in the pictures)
GND on TOP (solid shape): 14.6,41.3 28.12,41.3 28.12,46.81 28.68,46.81 28.68,40.74 14.04,40.74 14.04,53.44 1.56,53.44 1.56,1.56 76.37,1.56 76.37,1 1,1 1,54 14.6,54
GND on TOP (solid shape): 83.04,41.3 97.02,41.3 97.02,46.89 97.58,46.89 97.58,40.74 82.48,40.74 82.48,53.44 62.17,53.44 62.17,40.74 47.07,40.74 47.07,46.66 47.63,46.66 47.63,41.3 61.61,41.3 61.61,54 83.04,54
GND on TOP (solid shape): 152.4,41.3 165.92,41.3 165.92,47.03 166.48,47.03 166.48,40.74 151.84,40.74 151.84,53.44 130.61,53.44 130.61,40.74 115.97,40.74 115.97,46.84 116.53,46.84 116.53,41.3 130.05,41.3 130.05,54 152.4,54
GND on TOP (solid shape): 220.84,41.3 234.82,41.3 234.82,46.95 235.38,46.95 235.38,40.74 220.28,40.74 220.28,53.44 199.97,53.44 199.97,40.74 184.87,40.74 184.87,46.81 185.43,46.81 185.43,41.3 199.41,41.3 199.41,54 220.84,54
GND on TOP (solid shape): 358.64,41.3 372.62,41.3 372.62,47.01 373.18,47.01 373.18,41.27 372.65,40.74 358.08,40.74 358.08,53.44 337.77,53.44 337.77,40.74 322.67,40.74 322.67,46.79 323.23,46.79 323.23,41.3 337.21,41.3 337.21,54 358.64,54
GND on TOP (solid shape): 289.74,41.3 303.72,41.3 303.72,46.9 304.28,46.9 304.93,46.9 305.22,46.61 305.22,45.19 304.28,44.24 304.28,40.74 289.18,40.74 289.18,53.44 268.87,53.44 268.87,40.74 253.77,40.74 253.77,46.88 254.33,46.88 254.33,41.3 268.31,41.3 268.31,54 289.74,54
GND on TOP (solid shape): 421.69,1 346.26,1 346.26,1.56 375.68,1.56 375.82,1.42 378.49,1.42 378.63,1.56 380.15,1.56 380.28,1.68 380.28,4.12 380.41,4.26 383.05,4.26 383.29,4.02 383.29,2.11 383.84,1.56 421.13,1.56 421.13,53.44 406.21,53.44 406.21,40.74 391.57,40.74 391.57,46.87 392.13,46.87 392.13,41.3 405.65,41.3 405.65,54 421.69,54
GND on TOP (solid shape): 220.32,29.18 220.32,21.18 220.91,20.59 222.45,20.59 222.72,20.32 222.72,18.38 222.59,18.24 221.72,18.24 221.19,18.77 217.66,18.77 217.4,18.51 217.35,18.53 214.36,18.53 214.36,20.36 215.58,21.58 215.69,21.69 217.55,21.69 217.88,22.02 217.88,26.14 217.15,26.87 216.5,26.87 215.73,27.64 214.61,27.64 214.56,27.58 213.84,27.58 213.84,26.87 213.75,26.78 213.7,26.76 213.67,26.81 213.67,26.86 211.58,26.86 211.58,26.72 209.75,26.72 209.7,26.77 209.7,28.96 210.95,30.2 219.3,30.2
GND on TOP (solid shape): 104.46,40.94 104.46,40.81 104.63,40.64 105.92,40.64 106.04,40.51 106.04,39.37 106.05,38.61 106.04,37.34 106.05,37.21 105.82,36.98 104.94,36.98 104.94,35.92 105.79,35.92 105.79,34.25 106.22,33.82 110.72,33.82 110.72,32.93 111.79,32.93 111.79,33.82 112.22,33.82 112.6,33.44 112.6,29.47 112.38,29.25 111.58,29.25 111.48,29.35 111.48,29.92 111.5,29.94 111.57,29.94 111.76,30.14 111.79,30.14 111.79,30.16 111.8,30.17 111.8,31.37 111.79,31.38 111.79,32.09 110.72,32.09 110.72,32.01 110.66,31.91 110.56,31.92 110.5,31.96 110.28,32.18 105.52,32.18 104.61,31.27 104.17,31.27 104.17,32.09 103.28,32.09 103.28,33.99 103.67,34.38 103.67,40.98 103.68,40.99 104.42,40.99
GND on TOP (solid shape): 236,38.46 236.47,38.46 236.47,36.7 236.35,36.58 235.2,36.58 234.44,36.58 233.17,36.58 233.04,36.58 232.82,36.8 232.82,37.68 231.75,37.68 231.75,36.83 230.08,36.83 229.65,36.4 229.65,31.9 228.76,31.9 228.76,30.84 229.45,30.84 229.55,30.77 229.53,30.66 229.04,30.18 225.35,30.18 225.15,30.37 225.15,31.02 225.26,31.13 225.7,31.13 225.97,30.86 225.97,30.84 225.99,30.84 226,30.83 227.2,30.83 227.21,30.84 227.93,30.84 227.93,31.9 227.84,31.9 227.75,31.96 227.76,32.07 227.79,32.12 228.02,32.34 228.02,34.08 228.02,37.02 227.62,37.41 227.56,37.41 227.56,37.41 224.88,37.41 224.88,38.38 224.21,38.38 224.21,38.48 224.46,38.73 236,38.73
GND on TOP (solid shape): 98.46,39.09 98.46,38.46 99.09,38.46 99.44,38.11 99.44,37.08 99.31,36.96 98.17,36.96 98.17,36.96 97.41,36.96 97.41,36.96 96.14,36.96 96.01,36.96 95.78,37.19 95.78,38.06 94.72,38.06 94.72,37.21 93.05,37.21 92.62,36.78 92.62,32.28 91.73,32.28 91.73,31.22 92.42,31.22 92.52,31.15 92.49,31.04 92.06,30.61 88.33,30.61 88.05,30.89 88.05,31.42 88.15,31.52 88.72,31.52 88.74,31.5 88.74,31.44 88.94,31.24 88.94,31.22 88.96,31.22 88.97,31.21 90.17,31.21 90.18,31.22 90.89,31.22 90.89,32.28 90.81,32.28 90.72,32.34 90.72,32.45 90.76,32.5 90.98,32.72 90.98,34.46 90.98,34.46 90.98,37.4 90.59,37.79 90.53,37.79 90.53,37.8 87.85,37.8 87.85,38.76 87.17,38.76 87.17,38.86 87.43,39.12 98.43,39.12
GND on TOP (solid shape): 167.8,39.49 167.8,39.09 167.83,39.09 167.83,38.98 167.67,38.82 167.6,38.82 167.51,38.74 167.39,38.74 167.39,37.46 167.39,36.7 167.39,35.43 167.39,35.31 167.16,35.08 166.28,35.08 166.28,34.01 167.13,34.01 167.13,32.34 167.56,31.91 172.06,31.91 172.06,31.03 173.13,31.03 173.13,31.72 173.19,31.81 173.3,31.79 173.74,31.35 173.74,27.46 173.58,27.3 172.81,27.3 172.81,28.04 172.91,28.04 173.1,28.23 173.13,28.23 173.13,28.26 173.14,28.27 173.14,29.46 173.13,29.47 173.13,30.19 172.06,30.19 172.06,30.1 172,30.01 171.9,30.02 171.84,30.06 171.62,30.28 169.88,30.28 169.88,30.28 166.94,30.28 166.55,29.88 166.55,29.82 166.55,29.82 166.55,27.14 165.58,27.14 165.58,26.47 165.48,26.47 165.23,26.72 165.23,38.7 165.73,39.2 166.28,39.2 167.13,39.2 167.51,39.58 167.71,39.58
GND on TOP (solid shape): 37.24,38.86 37.3,38.95 37.41,38.93 37.54,38.8 37.68,38.8 37.74,38.73 38.61,38.73 38.73,38.61 38.73,37.46 38.73,37.46 38.73,36.7 38.73,36.7 38.73,35.43 38.73,35.31 38.51,35.08 37.63,35.08 37.63,34.01 38.48,34.01 38.48,32.34 38.91,31.91 39.66,31.91 39.67,31.9 41.23,31.9 41.24,31.91 43.41,31.91 43.41,31.03 44.48,31.03 44.48,31.72 44.54,31.81 44.65,31.79 45.29,31.15 45.29,27.56 45.07,27.34 44.27,27.34 44.17,27.45 44.17,28.02 44.19,28.04 44.26,28.04 44.45,28.23 44.48,28.23 44.48,28.26 44.49,28.27 44.49,29.46 44.48,29.47 44.48,30.19 43.41,30.19 43.41,30.1 43.35,30.01 43.25,30.02 43.19,30.06 42.97,30.28 41.23,30.28 41.23,30.28 38.29,30.28 37.9,29.88 37.9,29.82 37.9,29.82 37.9,27.14 36.93,27.14 36.93,26.47 36.83,26.47 36.58,26.72 36.58,33.32 36.25,33.66 36.25,38.26 37.24,38.26
GND on BOTTOM (solid shape): 202.32,1.38 202.33,1.38 202.33,1 80.19,1 80.19,1.56 202.32,1.56
GND on BOTTOM (solid shape): 342.52,1 206.2,1 206.2,1.38 206.2,1.38 206.2,1.56 342.52,1.56
GND on BOTTOM (solid shape): 14.6,41.3 28.12,41.3 28.12,44.52 28.68,44.52 28.68,40.74 14.04,40.74 14.04,53.44 1.56,53.44 1.56,1.56 76.31,1.56 76.31,1 1,1 1,54 14.6,54
GND on BOTTOM (solid shape): 421.69,1 346.44,1 346.44,1.56 421.13,1.56 421.13,53.44 406.21,53.44 406.21,40.74 391.57,40.74 391.57,46.93 392.13,46.93 392.13,41.3 405.65,41.3 405.65,54 421.69,54
GND on BOTTOM (solid shape): 83.04,41.3 97.02,41.3 97.02,44.66 97.58,44.66 97.58,40.74 82.48,40.74 82.48,53.44 62.17,53.44 62.17,40.74 47.07,40.74 47.07,46.47 47.63,46.47 47.63,41.3 61.61,41.3 61.61,54 83.04,54
GND on BOTTOM (solid shape): 220.84,41.3 234.82,41.3 234.82,44.58 235.38,44.58 235.38,40.74 220.28,40.74 220.28,53.44 199.97,53.44 199.97,40.74 184.87,40.74 184.87,46.94 185.43,46.94 185.43,41.3 199.41,41.3 199.41,54 220.84,54
GND on BOTTOM (solid shape): 289.74,41.3 303.72,41.3 303.72,44.67 304.28,44.67 304.28,40.74 289.18,40.74 289.18,53.44 268.87,53.44 268.87,40.74 253.77,40.74 253.77,46.93 254.33,46.93 254.33,41.3 268.31,41.3 268.31,54 289.74,54
GND on BOTTOM (solid shape): 358.64,41.3 372.62,41.3 372.62,44.12 373.18,44.12 373.18,40.74 358.08,40.74 358.08,53.44 337.77,53.44 337.77,40.74 322.67,40.74 322.67,46.94 323.23,46.94 323.23,41.3 337.21,41.3 337.21,54 358.64,54
GND on BOTTOM (solid shape): 152.4,41.3 165.92,41.3 165.92,46.34 166.12,46.54 167.26,46.54 167.4,46.41 167.4,45.22 167.1,44.93 166.69,44.93 166.48,44.71 166.48,40.74 151.84,40.74 151.84,53.44 130.61,53.44 130.61,40.74 115.97,40.74 115.97,46.73 116.53,46.73 116.53,41.3 130.05,41.3 130.05,54 152.4,54
GND on TOP: 380.32,1 380.04,1.28 380.04,4.08 380.25,4.29 382.6,4.29 383.33,5.02 388.68,5.02 388.96,4.75 388.96,2.52 389.47,2.01 399.02,2.01 401.25,4.25 412,4.25 414.66,6.9 414.66,18.56 408.88,24.34 408.88,34.21 405.77,37.31 398.52,37.31 396.22,39.61 396.22,39.93 392.23,39.93 391.57,40.59 391.57,40.93 391.87,41.23 405.71,41.23 405.82,41.34 405.82,53.62 406.18,53.98 421.31,53.98 421.62,53.67 421.62,1.29 421.33,1
GND on TOP: 207.21,18.74 207.65,19.18 209.04,19.18 209.3,18.92 209.3,16.89 209.04,16.64 206.38,16.64 206.12,16.89 206.12,17.71 206.21,17.8 207.12,17.8 207.21,17.89
GND on TOP: 203.43,23.6 203.43,21.85 201.49,19.91 201.38,19.91 201.38,18.97 204.71,15.63 204.71,14.63 204.16,14.08 184.09,14.08 183.58,14.58 183.58,15.58 192.39,24.39 202.64,24.39
GND on TOP: 26.8,26.47 26.54,26.72 26.54,38.78 27.31,39.55 29.15,39.55 30.17,40.56 30.73,40.56 30.8,40.49 30.8,39.34 30.43,38.97 29.06,38.97 28.7,38.61 28.7,37.46 28.7,36.7 28.7,35.43 28.7,35.31 28.47,35.08 27.6,35.08 27.6,34.01 28.45,34.01 28.45,32.34 28.88,31.91 33.38,31.91 33.38,31.03 34.44,31.03 34.44,31.72 34.51,31.81 34.62,31.79 34.87,31.53 34.87,27.48 34.78,27.39 34.27,27.39 34.14,27.52 34.14,27.96 34.42,28.23 34.44,28.23 34.44,28.26 34.45,28.27 34.45,29.46 34.44,29.47 34.44,30.19 33.38,30.19 33.38,30.1 33.32,30.01 33.21,30.02 33.16,30.06 32.94,30.28 31.2,30.28 31.2,30.28 28.26,30.28 27.87,29.88 27.87,29.82 27.86,29.82 27.86,27.14 26.9,27.14 26.9,26.47
GND on TOP: 390,4.34 394.79,4.34 399.27,8.81 406.12,8.81 407.36,10.05 407.36,20.24 406.37,21.23 403.25,21.23 402.98,21.5 402.98,22.06 403.18,22.26 403.23,22.26 403.58,22.61 409.11,22.61 414.15,17.56 414.15,7.95 411.23,5.03 399.98,5.03 397.28,2.34 390.04,2.34 389.57,2.81 389.57,3.91
GND on TOP: 51.56,35.31 67.69,35.31 72.82,30.18 72.82,29.67 72.44,29.29 51.51,29.29 51.05,29.74 51.05,34.8
GND on TOP: 115.96,40.73 115.96,45.17 116.11,45.33 116.41,45.33 116.51,45.22 116.51,41.28 130.07,41.28 130.07,53.98 152.38,53.98 152.38,41.28 165.94,41.28 165.94,43.72 166.06,43.84 166.42,43.84 166.49,43.77 166.49,40.73 151.1,40.73 147.37,44.45 147.37,48.23 145.87,49.73 135.74,49.73 134.52,48.51 134.52,40.68 127.31,33.47 127.31,30.89 126.84,30.42 126.13,30.42 123.77,32.77 123.77,38.03 121.08,40.73
GND on TOP: 175.49,38.73 176.78,38.73 176.91,38.61 176.91,35.31 176.66,35.05 176.66,32.34 177.09,31.91 182.7,31.91 183.46,31.15 183.46,27.54 183.33,27.41 181.56,27.41 181.51,27.46 181.51,27.92 181.63,28.04 182.43,28.04 182.66,28.27 182.66,29.46 182.41,29.71 181.71,29.71 181.14,30.28 176.53,30.28 176.07,29.82 176.07,26.57 175.97,26.47 175.01,26.47 174.75,26.72 174.75,37.19 174.37,37.57 174.37,38.89 174.52,39.04 175.18,39.04
GND on TOP: 51.56,40.73 47.06,40.73 47.06,44.67 47.21,44.83 47.47,44.83 47.61,44.69 47.61,41.28 61.63,41.28 61.63,53.98 83.02,53.98 83.02,41.28 97.04,41.28 97.04,44.13 97.09,44.18 97.49,44.18 97.59,44.07 97.59,40.73 83.48,40.73 82.19,40.73 79.3,43.61 79.3,48.92 78.56,49.66 66.67,49.66 65.79,48.77 65.79,39.37 64.9,38.48 53.81,38.48
GND on TOP: 1.02,1.02 1.02,53.98 14.58,53.98 14.58,41.28 28.14,41.28 28.14,44.05 28.29,44.21 28.59,44.21 28.69,44.1 28.69,42.93 28.69,40.73 19.73,40.73 19.71,40.73 5.52,40.73 3.96,39.17 3.94,39.17 3.94,12.06 8.76,7.24 27.94,7.24 32.13,11.43 42.29,11.43 42.67,11.05 42.67,6.86 43.69,5.84 45.85,5.84 47.24,7.24 47.24,12.19 46.1,13.34 20.45,13.34 19.81,13.97 19.81,15.49 20.57,16.26 48.13,16.26 52.2,20.32 56.77,20.32 56.9,20.19 56.9,19.3 53.39,15.79 53.39,5.84 57.21,2.01 74.84,2.01 75.28,1.57 75.52,1.38 75.78,1.2 75.82,1.09 75.72,1.02
GND on TOP: 190.23,41.19 199.4,41.19 199.49,41.29 199.49,53.64 199.83,53.98 220.49,53.98 220.77,53.7 220.77,40.78 220.55,40.55 214.84,40.55 214.46,40.93 214.46,48.48 213.47,49.48 204.73,49.48 204.16,48.91 204.16,40.99 204.41,40.74 204.41,29.84 203.03,28.46 193.39,28.46 192,29.86 192,38.71 190.18,40.53 190.18,41.14 ; 1 cut-out
GND on TOP: 381.63,33.15 387.86,33.15 388.75,32.26 388.75,28.96 388.24,28.45 387.22,28.45 387.22,30.99 386.21,30.99 385.57,31.62 380.8,31.62 379.22,33.2 379.22,36.45 378.33,37.34 378.33,39.37 377.82,39.88 377.82,41.53 378.46,42.16 379.86,42.16 380.24,41.78 380.24,40.77 380.49,40.51 380.49,34.29
GND on TOP: 311.89,29.4 318.16,29.4 319.28,28.28 319.28,24.18 318.06,22.96 315.02,22.96 314.78,23.19 314.78,23.74 314.96,23.92 316.34,23.92 317.2,24.78 317.2,27.65 317.11,27.74 315.09,27.74 314.94,27.89 312.33,27.89 312.27,27.95 311.18,27.95 310.37,28.76 310.37,30.34 309.5,31.21 309.5,31.88 309.12,32.26 309.12,37.22 309.95,38.06 311.29,38.06 311.46,37.89 311.46,37.13 311.35,37.02 311.35,32.61 311.46,32.5 311.46,29.82 311.88,29.4
GND on TOP: 137.41,45.98 144.22,45.98 150.85,39.35 160.51,39.35 161.36,38.5 161.36,32.76 156.56,27.96 149.7,27.96 144.77,32.89 140.59,32.89 139.99,33.49 137.71,33.49 137.14,34.06 131.51,34.06 131.06,34.51 131.06,35.27 137.02,41.23 137.02,45.59
GND on TOP: outline of 103 points within 80.63,1.02 375.37,53.95 ; 9 cut-outs
GND on TOP: 368.53,39.3 370.61,39.3 370.78,39.13 370.78,34.34 370.55,34.11 370.55,33.05 371.53,32.06 377.56,32.06 377.76,32.26 378.46,32.26 378.75,31.97 378.75,27.79 378.29,27.33 377.74,27.33 377.5,27.57 377.5,28.55 377.67,28.72 377.67,30.66 377.58,30.75 376.1,30.75 376,30.64 369.92,30.64 368.04,32.52 368.04,38.82
GND on TOP: 307.72,29.88 309.48,29.88 310.02,29.35 310.02,27.23 310.16,27.09 310.16,24.25 309.23,23.32 306.27,23.32 306.06,23.53 306.06,24.22 306.91,25.06 308.51,25.06 308.95,25.51 308.95,28.02 308.64,28.33 301.7,28.33 300.05,29.97 300.05,38.18 300.39,38.51 302,38.51 302.25,38.26 302.25,37.43 302.1,37.28 302.1,33.59 301.85,33.34 301.85,30.42 302.46,29.81 307.65,29.81
GND on TOP: 243.08,41.4 243.08,38.3 242.32,37.54 242.32,35.13 242.74,34.71 248.87,34.71 249.63,33.94 249.63,30.28 249.45,30.09 248.99,30.09 248.83,30.25 248.83,32.25 248.58,32.5 247.88,32.5 247.31,33.07 242.27,33.07 241.81,32.62 241.08,32.62 240.58,33.12 240.58,40.93 240.59,40.94 240.59,42.44 240.8,42.65 242.31,42.65 242.4,42.56 242.4,42.08
GND on BOTTOM: 130.84,10.23 129.51,8.89 128.48,8.89 128.35,9.02 128.35,10.85 128.94,11.45 128.94,11.68 128.53,12.1 125.65,12.1 125.15,12.6 125.15,13.45 125.98,14.27 129.57,14.27 130.28,13.56 130.69,13.56 130.89,13.36 130.89,12.7 130.84,12.66
GND on BOTTOM: outline of 199 points within 1,1.04 421.59,54 ; 1 cut-out
GND on BOTTOM: 303.89,55.9 305.28,55.9 305.34,55.85 305.34,45.28 304.98,44.93 303.91,44.93 303.76,45.08 303.76,55.77
GND on BOTTOM: 104.89,55.55 106.09,55.55 106.26,55.37 106.26,47.32 106.46,47.13 106.86,47.13 107.03,46.96 107.03,45.77 106.7,45.44 105.32,45.44 104.74,46.03 104.74,55.4
GND on BOTTOM: 28.28,55.91 29.67,55.91 29.72,55.85 29.72,45.29 29.37,44.93 28.3,44.93 28.15,45.09 28.15,55.78
GND on BOTTOM: 372.79,55.38 374.18,55.38 374.24,55.33 374.24,44.76 373.88,44.41 372.81,44.41 372.66,44.56 372.66,55.25
GND on BOTTOM: 97.18,55.91 98.57,55.91 98.62,55.85 98.62,45.29 98.27,44.93 97.2,44.93 97.05,45.09 97.05,55.78
GND on BOTTOM: 129.59,24.33 131.92,24.33 132.04,24.45 132.04,25.57 131.65,25.96 126.72,25.96 126.59,25.83 126.59,25.58 126.84,25.34 128.24,25.34 128.44,25.15 128.78,25.15
GND on BOTTOM: 234.98,55.91 236.37,55.91 236.42,55.85 236.42,45.29 236.07,44.93 235,44.93 234.85,45.09 234.85,55.78
GND on BOTTOM: 242.69,55.55 243.89,55.55 244.06,55.37 244.06,47.32 244.26,47.13 244.66,47.13 244.83,46.96 244.83,45.77 244.5,45.44 243.12,45.44 242.54,46.03 242.54,55.4
GND on BOTTOM: 166.08,55.91 167.47,55.91 167.52,55.85 167.52,45.29 167.17,44.93 166.1,44.93 165.95,45.09 165.95,55.78
GND on BOTTOM: 338.29,10.3 355.05,10.3 363.45,1.9 363.45,1.76 362.77,1.08 149.08,1.08 148.99,1.17 148.99,2.32 150.35,3.69 176.25,3.69 181.31,8.75 224.64,8.75 225.84,7.55 243.73,7.55 246.7,10.52 292.93,10.52 295.16,8.28 329.08,8.28 331.18,10.37 338.22,10.37
GND on BOTTOM: 311.6,55.55 312.8,55.55 312.97,55.37 312.97,47.32 313.17,47.12 313.57,47.12 313.74,46.96 313.74,45.77 313.41,45.44 312.04,45.44 311.45,46.02 311.45,55.39
GND on BOTTOM: 35.99,55.55 37.19,55.55 37.36,55.37 37.36,47.32 37.56,47.13 37.96,47.13 38.13,46.96 38.13,45.77 37.8,45.44 36.42,45.44 35.84,46.03 35.84,55.4
GND on BOTTOM: 380.5,55.03 381.7,55.03 381.87,54.85 381.87,46.8 382.07,46.6 382.47,46.6 382.64,46.44 382.64,45.25 382.31,44.92 380.94,44.92 380.35,45.5 380.35,54.87
GND on BOTTOM: 173.79,55.55 174.99,55.55 175.16,55.37 175.16,47.32 175.36,47.13 175.76,47.13 175.93,46.96 175.93,45.77 175.6,45.44 174.22,45.44 173.64,46.03 173.64,55.4
GND on G2: 1,1 1,54 14.6,54 14.6,41.3 28.12,41.3 28.12,55.9 28.33,56.11 47.42,56.11 47.63,55.9 47.63,41.3 61.61,41.3 61.61,54 83.04,54 83.04,41.3 97.02,41.3 97.02,55.9 97.23,56.11 116.32,56.11 116.53,55.9 116.53,41.3 130.05,41.3 130.05,54 152.4,54 152.4,41.3 165.92,41.3 165.92,55.9 166.13,56.11 185.22,56.11 185.43,55.9 185.43,41.3 199.41,41.3 199.41,54 220.84,54 220.84,41.3 234.82,41.3 234.82,55.9 235.03,56.11 254.12,56.11 254.33,55.9 254.33,41.3 268.31,41.3 268.31,54 289.74,54 289.74,41.3 303.72,41.3 303.72,55.9 303.93,56.11 323.02,56.11 323.23,55.9 323.23,41.3 337.21,41.3 337.21,54 358.64,54 358.64,41.3 372.62,41.3 372.62,55.9 372.83,56.11 391.92,56.11 392.13,55.9 392.13,41.3 405.65,41.3 405.65,54 421.69,54 421.69,1
GND on V3: 1,1 1,54 14.6,54 14.6,41.3 28.12,41.3 28.12,55.9 28.33,56.11 47.42,56.11 47.63,55.9 47.63,41.3 61.61,41.3 61.61,54 83.04,54 83.04,41.3 97.02,41.3 97.02,55.9 97.23,56.11 116.32,56.11 116.53,55.9 116.53,41.3 130.05,41.3 130.05,54 152.4,54 152.4,41.3 165.92,41.3 165.92,55.9 166.13,56.11 185.22,56.11 185.43,55.9 185.43,41.3 199.41,41.3 199.41,54 220.84,54 220.84,41.3 234.82,41.3 234.82,55.9 235.03,56.11 254.12,56.11 254.33,55.9 254.33,41.3 268.31,41.3 268.31,54 289.74,54 289.74,41.3 303.72,41.3 303.72,55.9 303.93,56.11 323.02,56.11 323.23,55.9 323.23,41.3 337.21,41.3 337.21,54 358.64,54 358.64,41.3 372.62,41.3 372.62,55.9 372.83,56.11 391.92,56.11 392.13,55.9 392.13,41.3 405.65,41.3 405.65,54 421.69,54 421.69,1 ; 4 cut-outs
GND_1 on TOP (solid shape): outline of 235 points within 17.72,24.5 24.73,31.5
GND_1 on BOTTOM (solid shape): outline of 235 points within 17.72,24.5 24.73,31.5
GND_2 on TOP (solid shape): outline of 235 points within 74.72,35.5 81.73,42.5
GND_2 on BOTTOM (solid shape): outline of 235 points within 74.72,35.5 81.73,42.5
GND_3 on TOP (solid shape): outline of 235 points within 200.72,35.5 207.73,42.5
GND_3 on BOTTOM (solid shape): outline of 235 points within 200.72,35.5 207.73,42.5
GND_5 on TOP (solid shape): outline of 235 points within 200.72,1.5 207.73,8.5
GND_5 on BOTTOM (solid shape): outline of 235 points within 200.72,1.5 207.73,8.5
GND_6 on TOP (solid shape): outline of 235 points within 74.72,1.5 81.73,8.5
GND_6 on BOTTOM (solid shape): outline of 235 points within 74.72,1.5 81.73,8.5
GND_7 on TOP (solid shape): outline of 235 points within 340.96,1.5 347.97,8.5
GND_7 on BOTTOM (solid shape): outline of 235 points within 340.96,1.5 347.97,8.5
GND_8 on TOP (solid shape): outline of 235 points within 340.96,35.5 347.97,42.5
GND_8 on BOTTOM (solid shape): outline of 235 points within 340.96,35.5 347.97,42.5
GND_9 on TOP (solid shape): outline of 235 points within 397.96,24.5 404.97,31.5
GND_9 on BOTTOM (solid shape): outline of 235 points within 397.96,24.5 404.97,31.5
VCC_12P_FAN1_IN on TOP: 32.66,36.82 32.66,35.03 31.11,33.48 31.11,32.18 31.09,32.16 29.74,32.16 29.71,32.19 29.02,32.19 28.75,32.46 28.75,34.72 29.46,35.43 29.46,38.59 29.62,38.74 30.69,38.74 31.05,39.11 31.05,40.35 30.65,40.75 30.65,42.54 31.62,43.5 34.01,43.5 34.36,43.16 34.36,38.38 32.97,37 32.84,37
VCC_12P_FAN1_IN on BOTTOM: 30.74,55.32 30.82,55.4 32.19,55.4 32.29,55.3 32.29,47.32 32.62,46.99 32.62,43.7 33.25,43.07 33.25,38.84 32.82,38.4 29.46,38.4 29.09,38.78 29.09,44.3 30,45.21 30,46.66 30.74,47.4
VCC_12P_FAN1_OUT on TOP (solid shape): 39.27,44.12 39.27,42.99 39.29,42.97 39.29,42.84 39.42,42.84 39.68,42.58 40.33,42.58 40.51,42.4 40.51,42.39 40.76,42.08 41.15,42.03 41.18,42.03 41.66,41.55 41.66,41.53 41.68,41.53 42.71,40.5 42.71,37.49 42.73,37.48 42.73,37.02 42.7,36.99 42.7,35.03 41.15,33.48 41.15,33.39 41.14,33.38 41.14,32.62 41.14,32.58 41.15,32.54 41.15,32.2 39.5,32.2 39.5,32.19 39.05,32.19 38.79,32.46 38.79,34.01 39.59,34.01 39.59,35.08 39.39,35.08 39.29,35.14 39.32,35.25 39.5,35.43 39.5,35.43 39.5,36.7 39.5,36.7 39.5,37.46 39.5,37.46 39.5,38.74 39.48,38.74 39.17,39.05 37.78,39.05 37.73,39.1 37.61,39.18 37.48,39.23 37.47,39.23 37.28,39.42 37.24,39.42 37.24,40.22 36.17,40.22 36.17,39.42 35.94,39.42 34.98,40.39 34.98,44.28 35.2,44.5 38.89,44.5
VCC_12P_FAN1_OUT on BOTTOM: 33,43.93 33,47.01 33.29,47.29 33.29,55.23 33.45,55.4 34.73,55.4 34.82,55.3 34.82,47.32 35.57,46.58 35.57,45.85 36.4,45.01 38.2,45.01 38.81,44.41 38.81,41.52 38.24,40.95 35.97,40.95
VCC_12P_FAN2_IN on TOP (solid shape): 103.17,42.45 103.17,35.97 99.71,32.51 97.97,32.51 97.49,32.99 95.73,32.99 94.18,34.54 94.1,34.54 94.09,34.55 93.32,34.55 93.28,34.55 93.24,34.54 92.9,34.54 92.9,36.2 92.9,36.2 92.9,36.64 93.17,36.91 94.72,36.91 94.72,36.11 95.78,36.11 95.78,36.3 95.85,36.4 95.96,36.38 96.14,36.2 96.14,36.19 97.41,36.19 97.41,36.2 98.17,36.2 98.17,36.19 99.44,36.19 99.44,36.21 99.85,36.62 99.85,38.46 100.42,38.46 100.42,39.52 99.54,39.52 99.3,39.77 99.3,40.27 99.33,40.3 99.33,42.13 100.14,42.94 102.69,42.94
VCC_12P_FAN2_IN on BOTTOM: 99.64,55.32 99.72,55.4 101.09,55.4 101.19,55.3 101.19,47.32 101.52,46.99 101.52,42.73 102.15,42.1 102.15,39.82 101.43,39.1 99.2,39.1 97.99,40.31 97.99,44.3 98.9,45.21 98.9,46.66 99.64,47.4
VCC_12P_FAN2_OUT on TOP (solid shape): 106.35,45.43 106.51,45.43 106.52,45.43 106.72,45.39 106.92,45.43 106.93,45.43 107.59,45.43 108.19,44.83 108.19,43.34 108.49,43.34 108.56,43.28 109.53,43.28 110.01,42.81 110.01,36.93 108.46,35.38 108.46,35.3 108.45,35.29 108.45,34.52 108.45,34.48 108.46,34.44 108.46,34.1 106.81,34.1 106.36,34.1 106.1,34.37 106.1,35.92 106.9,35.92 106.9,36.98 106.7,36.98 106.6,37.05 106.63,37.16 106.81,37.34 106.81,37.34 106.81,38.61 106.81,39.37 106.81,40.64 106.81,40.75 106.64,40.91 105.81,40.91 105.63,41.1 105.63,42.06 104.59,42.06 102.75,43.9 102.75,45.45 103.44,46.15 105.64,46.15
VCC_12P_FAN2_OUT on BOTTOM: 101.9,47.01 102.19,47.29 102.19,55.23 102.35,55.4 103.63,55.4 103.72,55.3 103.72,47.32 104.47,46.58 104.47,45.85 105.3,45.01 107.1,45.01 107.71,44.41 107.71,41.52 107.14,40.95 104.04,40.95 101.9,43.09
VCC_12P_FAN3_IN on TOP (solid shape): 172.29,42.47 172.29,37.9 171.35,36.96 171.35,35.03 169.8,33.48 169.8,33.39 169.79,33.38 169.79,32.62 169.79,32.58 169.8,32.54 169.8,32.2 168.15,32.2 168.15,32.19 167.7,32.19 167.44,32.46 167.44,34.01 168.24,34.01 168.24,35.08 168.04,35.08 167.94,35.14 167.97,35.25 168.15,35.43 168.15,36.7 168.15,37.46 168.15,38.7 168.54,39.09 169.76,39.09 169.76,40.16 168.88,40.16 168.38,40.66 168.38,42.32 169.44,43.38 171.37,43.38
VCC_12P_FAN3_IN on BOTTOM: 168.54,55.32 168.62,55.4 169.99,55.4 170.09,55.3 170.09,47.32 170.42,46.99 170.42,42.24 170.78,41.88 170.78,40.38 169.93,39.52 167.22,39.52 166.89,39.85 166.89,44.3 167.8,45.21 167.8,46.66 168.54,47.4
VCC_12P_FAN3_OUT on TOP (solid shape): 177.01,43.05 178.31,43.05 180.87,40.49 180.87,35.03 179.32,33.48 179.32,33.39 179.32,33.38 179.32,32.62 179.32,32.58 179.32,32.54 179.32,32.2 177.67,32.2 177.67,32.19 177.23,32.19 176.96,32.46 176.96,34.01 177.76,34.01 177.76,35.08 177.56,35.08 177.47,35.14 177.49,35.25 177.67,35.43 177.67,35.43 177.67,36.7 177.67,36.7 177.67,37.46 177.67,37.46 177.67,38.74 177.57,38.74 177.22,39.09 175.81,39.09 175.41,39.49 175.41,40.22 174.35,40.22 174.35,39.52 173,39.52 172.67,39.85 172.67,43.64 173.08,44.04 176.02,44.04
VCC_12P_FAN3_OUT on BOTTOM: 170.8,47.01 171.09,47.29 171.09,55.23 171.25,55.4 172.53,55.4 172.62,55.3 172.62,47.32 173.37,46.58 173.37,45.85 174.2,45.01 176,45.01 176.61,44.41 176.61,41.52 176.04,40.95 172.53,40.95 170.8,42.69
